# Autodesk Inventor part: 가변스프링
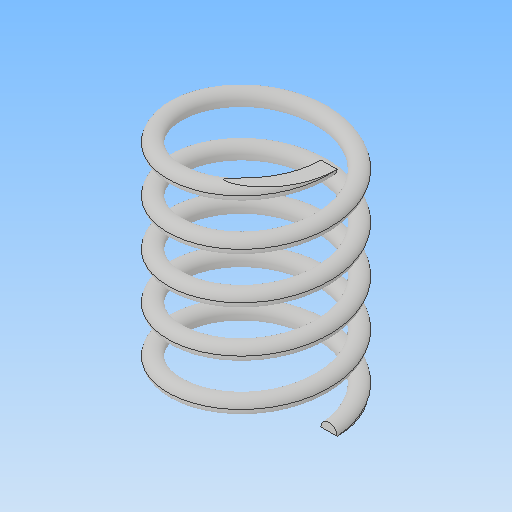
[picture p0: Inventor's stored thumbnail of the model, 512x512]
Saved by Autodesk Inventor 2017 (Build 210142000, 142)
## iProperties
Part Number: 가변스프링
Material: 일반
Document SubType Name: Modeling
Designer: MRC
Density: 1 g/cm^3
Appearance: 기본값
Mass: 0.875037 g
Surface Area: 17.7541 cm^2
Volume: 0.875037 cm^3
Author: MRC
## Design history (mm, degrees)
sketch "스케치1"
  geometry: L1 (0, 0)-(0, 28.5); L2 (0, 28.5)-(9, 28.5); L3 (0, 0)-(9, 0); C1 r 1 at (9, 0)
  constraints: 6 end point, 2 horizontal, 1 centre point, 1 coincident, 1 vertical
  dimensions: "d0" = 28.5 distance of L1.start L1.end (derived); "d1" = 9 distance of L1.end L2.end; "d2" = 9 distance of L1.start L3.end; "d3" = 2 diameter of C1
feature "코일1" sketch "스케치1" pitch "d4" = 10; turns "d6" = 5; dims "d5" = 28.5 (= d0), "d7" = 0, angle "d8" = 90 deg, angle "d9" = 90 deg, "d10" = 0, "d11" = 0
sketch "스케치2"
  geometry: L1 (28.5, 12.5)-(0, 12.5); L2 (0, 12.5)-(0, -12.5); L3 (0, -12.5)-(28.5, -12.5); L4 (28.5, -12.5)-(28.5, 12.5); 2 further points
  constraints: 8 end point, 2 parallel, 1 coincident, 1 horizontal, 1 midpoint, 1 perpendicular
  dimensions: "d12" = 28.5 distance of L2.end L3.end (= d0); "d13" = 25 distance of L3.end L1.start
extrude "돌출1" sketch "스케치2" stored distance "d14" = 0; taper "d15" = 0 deg
node "솔리드1"
